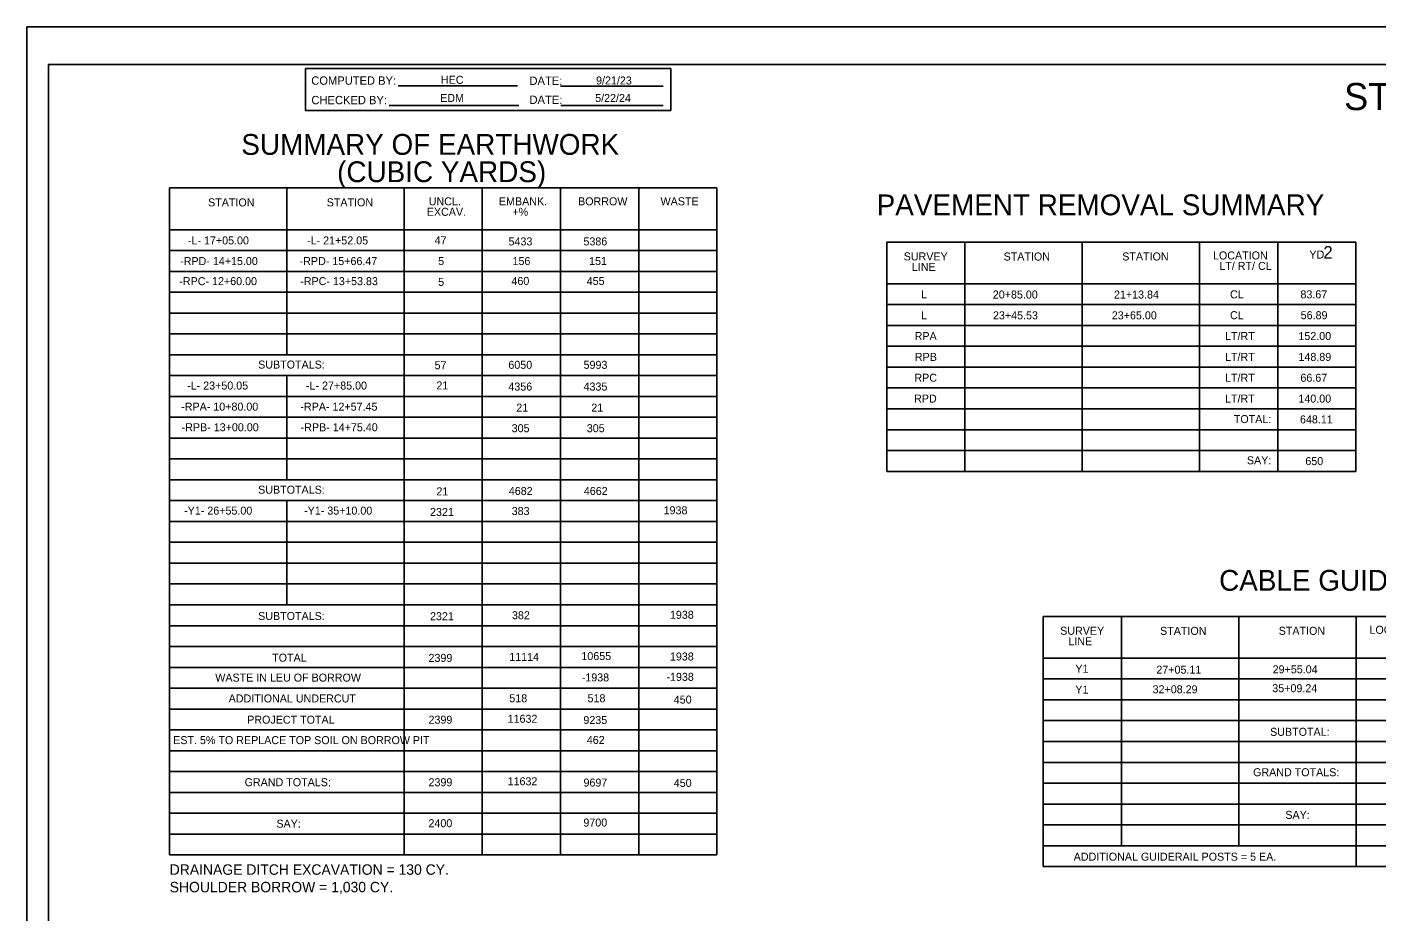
# Model space of a CAD drawing. Extents: x 2820318 to 2824860, y 680532 to 681838.
# Drawn here: x 2822504 to 2823312, y 681101 to 681632 of the extents above; entities that cross this region are included whole.
import ezdxf

# ---------------------------------------------------------------- set-up
doc = ezdxf.new("R2010")
doc.units = 0
for name, color, linetype in [('Default', 7, 'Continuous'), ('Sheet Cutting Line CELL', 7, 'Continuous'), ('Sheet Plot Border Inside CELL', 7, 'Continuous'), ('Sheet Plot Border Outside CELL', 7, 'Continuous'), ('Sheet Summary Combination CELL', 7, 'Continuous'), ('Sheet Summary Combination Grid CELL', 7, 'Continuous'), ('Sheet Summary Earthwork CELL', 7, 'Continuous')]:
    doc.layers.add(name, color=color, linetype=linetype)

msp = doc.modelspace()

# ---------------------------------------------------------------- linework, layer by layer
at = {"layer": 'Default'}
msp.add_lwpolyline([(2822503.58, 681631.51), (2822503.58, 680531.51), (2824187.58, 680531.51), (2824187.58, 681631.51)], close=True, dxfattribs=at)
msp.add_lwpolyline([(2822503.58, 681631.51), (2822503.58, 680531.51), (2824187.58, 680531.51), (2824187.58, 681631.51)], close=True, dxfattribs=at)
at = {"layer": 'Sheet Cutting Line CELL'}
for p, q in [((2824187.58, 681631.51), (2822503.58, 681631.51)), ((2822503.58, 681631.51), (2822503.58, 680531.51))]:
    msp.add_line(p, q, dxfattribs=at)
at = {"layer": 'Sheet Plot Border Inside CELL'}
msp.add_lwpolyline([(2824183.08, 681609.06), (2822516.58, 681609.06), (2822516.58, 680553.96), (2824183.08, 680553.96)], close=True, dxfattribs=at)
at = {"layer": 'Sheet Plot Border Outside CELL'}
msp.add_lwpolyline([(2824187.58, 681631.51), (2822503.58, 681631.51), (2822503.58, 680531.51), (2824187.58, 680531.51)], close=True, dxfattribs=at)
at = {"layer": 'Sheet Summary Combination CELL'}
for p, q in [((2822726.23, 681596.11), (2822797.78, 681596.11)), ((2822823.58, 681595.96), (2822884.98, 681595.96)), ((2822720.78, 681584.41), (2822798.48, 681584.41)), ((2822823.73, 681584.46), (2822885.13, 681584.46)), ((2822683.37, 681534.89), (2822683.37, 681534.89)), ((2822689.62, 681534.79), (2822689.62, 681534.79)), ((2822698.67, 681534.99), (2822698.67, 681534.99)), ((2822704.27, 681534.89), (2822704.27, 681534.89)), ((2823160.38, 681502.44), (2823160.38, 681502.44)), ((2823175.68, 681502.54), (2823175.68, 681502.54)), ((2823181.28, 681502.44), (2823181.28, 681502.44)), ((2823166.63, 681502.34), (2823166.63, 681502.34)), ((2823254.21, 681277.92), (2823254.21, 681277.92)), ((2823260.46, 681277.82), (2823260.46, 681277.82)), ((2823269.51, 681278.02), (2823269.51, 681278.02)), ((2823275.11, 681277.92), (2823275.11, 681277.92))]:
    msp.add_line(p, q, dxfattribs=at)
msp.add_lwpolyline([(2822670.58, 681606.51), (2822889.58, 681606.51), (2822889.58, 681581.51), (2822670.58, 681581.51)], close=True, dxfattribs=at)
at = {"layer": 'Sheet Summary Combination Grid CELL'}
for p, q in [((2822589.02, 681534.94), (2822917.27, 681534.94)), ((2822589.02, 681534.94), (2822589.02, 681134.94)), ((2822659.37, 681534.94), (2822659.37, 681434.94)), ((2822729.67, 681534.94), (2822729.67, 681134.94)), ((2822776.57, 681534.94), (2822776.57, 681134.94)), ((2822823.47, 681534.94), (2822823.47, 681134.94)), ((2822870.37, 681534.94), (2822870.37, 681134.94)), ((2822917.27, 681534.94), (2822917.27, 681134.94)), ((2822589.02, 681509.94), (2822917.27, 681509.94)), ((2823019.13, 681502.49), (2823300.48, 681502.49)), ((2823019.13, 681502.49), (2823019.13, 681364.99)), ((2823066.03, 681502.49), (2823066.03, 681364.99)), ((2823136.38, 681502.49), (2823136.38, 681364.99)), ((2823206.68, 681502.49), (2823206.68, 681364.99)), ((2823253.58, 681502.49), (2823253.58, 681364.99)), ((2823300.48, 681502.49), (2823300.48, 681364.99)), ((2822589.02, 681497.44), (2822917.27, 681497.44)), ((2822589.02, 681484.94), (2822917.27, 681484.94)), ((2822589.02, 681472.44), (2822917.27, 681472.44)), ((2823019.13, 681477.49), (2823300.48, 681477.49)), ((2823019.13, 681464.99), (2823300.48, 681464.99)), ((2822589.02, 681459.94), (2822917.27, 681459.94)), ((2822589.02, 681447.44), (2822917.27, 681447.44)), ((2823019.13, 681452.49), (2823300.48, 681452.49)), ((2823019.13, 681439.99), (2823300.48, 681439.99)), ((2823019.13, 681439.99), (2823300.48, 681439.99)), ((2822589.02, 681434.94), (2822917.27, 681434.94)), ((2822589.02, 681422.44), (2822917.27, 681422.44)), ((2822659.37, 681422.44), (2822659.37, 681359.94)), ((2823019.13, 681427.49), (2823300.48, 681427.49)), ((2823019.13, 681414.99), (2823300.48, 681414.99)), ((2822589.02, 681409.94), (2822917.27, 681409.94)), ((2822589.02, 681397.44), (2822917.27, 681397.44)), ((2823019.13, 681402.49), (2823300.48, 681402.49)), ((2823019.13, 681402.49), (2823300.48, 681402.49)), ((2823019.13, 681402.49), (2823300.48, 681402.49)), ((2823019.13, 681389.99), (2823300.48, 681389.99)), ((2822589.02, 681384.94), (2822917.27, 681384.94)), ((2823019.13, 681377.49), (2823300.48, 681377.49)), ((2822589.02, 681372.44), (2822917.27, 681372.44)), ((2823019.13, 681364.99), (2823300.48, 681364.99)), ((2822589.02, 681359.94), (2822917.27, 681359.94)), ((2822589.02, 681347.44), (2822917.27, 681347.44)), ((2822659.37, 681347.44), (2822659.37, 681284.94)), ((2822589.02, 681334.94), (2822917.27, 681334.94)), ((2822589.02, 681322.44), (2822917.27, 681322.44)), ((2822589.02, 681309.94), (2822917.27, 681309.94)), ((2822589.02, 681297.44), (2822917.27, 681297.44)), ((2822589.02, 681284.94), (2822917.27, 681284.94)), ((2823112.96, 681277.97), (2823597.97, 681277.97)), ((2823112.96, 681277.97), (2823112.96, 681127.97)), ((2823159.86, 681277.97), (2823159.86, 681140.47)), ((2823230.21, 681277.97), (2823230.21, 681140.47)), ((2823300.51, 681277.97), (2823300.51, 681127.97)), ((2822589.02, 681272.44), (2822917.27, 681272.44)), ((2822589.02, 681272.44), (2822917.27, 681272.44)), ((2822589.02, 681259.94), (2822917.27, 681259.94)), ((2823112.96, 681252.97), (2823597.97, 681252.97)), ((2822589.02, 681247.44), (2822917.27, 681247.44)), ((2823112.96, 681240.47), (2823597.97, 681240.47)), ((2822589.02, 681234.94), (2822917.27, 681234.94)), ((2823112.96, 681227.97), (2823551.07, 681227.97)), ((2823112.96, 681227.97), (2823597.97, 681227.97)), ((2822589.02, 681222.44), (2822917.27, 681222.44)), ((2822589.02, 681222.44), (2822917.27, 681222.44)), ((2823112.96, 681215.47), (2823597.97, 681215.47)), ((2822589.02, 681209.94), (2822917.27, 681209.94)), ((2822589.02, 681209.94), (2822917.27, 681209.94)), ((2822589.02, 681197.44), (2822917.27, 681197.44)), ((2823112.96, 681202.97), (2823597.97, 681202.97)), ((2823112.96, 681190.47), (2823597.97, 681190.47)), ((2822589.02, 681184.94), (2822917.27, 681184.94)), ((2822589.02, 681184.94), (2822917.27, 681184.94)), ((2822589.02, 681172.44), (2822917.27, 681172.44)), ((2822589.02, 681172.44), (2822917.27, 681172.44)), ((2823112.96, 681177.97), (2823597.97, 681177.97)), ((2823112.96, 681165.47), (2823597.97, 681165.47)), ((2822589.02, 681159.94), (2822917.27, 681159.94)), ((2822589.02, 681159.94), (2822917.27, 681159.94)), ((2822589.02, 681147.44), (2822917.27, 681147.44)), ((2822589.02, 681147.44), (2822917.27, 681147.44)), ((2823112.96, 681152.97), (2823597.97, 681152.97)), ((2823112.96, 681140.47), (2823551.07, 681140.47)), ((2823112.96, 681140.47), (2823597.97, 681140.47)), ((2822589.02, 681134.94), (2822917.27, 681134.94)), ((2822589.02, 681134.94), (2822917.27, 681134.94)), ((2823112.96, 681127.97), (2823597.97, 681127.97))]:
    msp.add_line(p, q, dxfattribs=at)

# ---------------------------------------------------------------- texts
at = {"layer": 'Sheet Summary Combination CELL'}
for s, height, p in [('COMPUTED BY:', 4.9998, (2822674.03, 681596.86)), ('HEC', 4.8, (2822751.79, 681597.41)), ('DATE:', 5, (2822804.88, 681596.76)), ('9/21/23', 4.8, (2822844.82, 681597.04)), ('5/22/24', 4.8, (2822844.27, 681586.5)), ('STATE OF NORTH CAROLINA', 16.2501, (2823293.33, 681581.66)), ('CHECKED BY:', 4.9998, (2822674.13, 681585.16)), ('EDM', 4.8, (2822751.33, 681586.53)), ('DATE:', 5, (2822804.88, 681585.36)), ('STATION', 4.8, (2822612.17, 681523.9)), ('STATION', 4.8, (2822683.31, 681523.92)), ('UNCL.', 4.8, (2822744.47, 681524.54)), ('EMBANK.', 4.8, (2822786.57, 681524.54)), ('BORROW', 4.8, (2822834.03, 681524.54)), ('WASTE', 4.8, (2822883.48, 681524.54)), ('EXCAV.', 4.8, (2822743.32, 681518.24)), ('+%', 4.8, (2822794.64, 681518.24)), ('-L- 17+05.00', 4.8, (2822600.09, 681501.1)), ('-L- 21+52.05', 4.8, (2822671.55, 681501.1)), ('47', 4.8, (2822748.01, 681501.19)), ('5433', 4.8, (2822792.33, 681500.5)), ('5386', 4.8, (2822837.24, 681500.5)), ('SURVEY', 4.8, (2823029.28, 681491.51)), ('STATION', 4.8, (2823089.18, 681491.45)), ('STATION', 4.8, (2823160.32, 681491.47)), ('LOCATION', 4.8, (2823214.74, 681492.09)), ('-RPD- 14+15.00', 4.8, (2822595.44, 681488.71)), ('-RPD- 15+66.47', 4.8, (2822667.07, 681488.71)), ('5', 4.8, (2822750.11, 681488.71)), ('156', 4.8, (2822794.72, 681488.71)), ('151', 4.8, (2822840.64, 681488.76)), ('LINE', 4.8, (2823034.18, 681485.21)), ('LT/ RT/ CL', 4.8, (2823218.52, 681485.79)), ('-RPC- 12+60.00', 4.8, (2822594.93, 681476.67)), ('-RPC- 13+53.83', 4.8, (2822667.42, 681476.67)), ('5', 4.8, (2822750.11, 681476.21)), ('460', 4.8, (2822794.07, 681476.76)), ('455', 4.8, (2822839.22, 681476.76)), ('L', 4.8, (2823039.67, 681468.74)), ('20+85.00', 4.8, (2823082.71, 681468.65)), ('21+13.84', 4.8, (2823155.36, 681468.65)), ('CL', 4.8, (2823224.97, 681468.74)), ('83.67', 4.8, (2823267.17, 681468.74)), ('L', 4.8, (2823039.67, 681456.24)), ('23+45.53', 4.8, (2823082.82, 681456.15)), ('23+65.00', 4.8, (2823154.08, 681456.15)), ('CL', 4.8, (2823224.97, 681456.24)), ('56.89', 4.8, (2823267.32, 681456.24)), ('RPA', 4.8, (2823035.86, 681443.74)), ('LT/RT', 4.8, (2823221.96, 681443.74)), ('152.00', 4.8, (2823265.95, 681443.74)), ('SUBTOTALS:', 4.8, (2822642.19, 681426.63)), ('57', 4.8, (2822748.01, 681426.24)), ('6050', 4.8, (2822792.23, 681426.5)), ('5993', 4.8, (2822837.33, 681426.5)), ('RPB', 4.8, (2823035.99, 681431.24)), ('LT/RT', 4.8, (2823221.96, 681431.24)), ('148.89', 4.8, (2823265.99, 681431.24)), ('RPC', 4.8, (2823035.7, 681418.74)), ('LT/RT', 4.8, (2823221.96, 681418.74)), ('66.67', 4.8, (2823267.17, 681418.74)), ('-L- 23+50.05', 4.8, (2822599.61, 681414.05)), ('-L- 27+85.00', 4.8, (2822670.88, 681414.05)), ('21', 4.8, (2822749.06, 681414.14)), ('4356', 4.8, (2822792.24, 681413.45)), ('4335', 4.8, (2822837.32, 681413.45)), ('-RPA- 10+80.00', 4.8, (2822596.05, 681401.4)), ('-RPA- 12+57.45', 4.8, (2822667.52, 681401.4)), ('21', 4.8, (2822796.97, 681400.8)), ('21', 4.8, (2822841.97, 681400.8)), ('RPD', 4.8, (2823035.52, 681406.24)), ('LT/RT', 4.8, (2823221.96, 681406.24)), ('140.00', 4.8, (2823265.95, 681406.24)), ('TOTAL:', 4.8, (2823227.23, 681393.94)), ('648.11', 4.8, (2823266.9, 681393.74)), ('-RPB- 13+00.00', 4.8, (2822596.32, 681389.05)), ('-RPB- 14+75.40', 4.8, (2822667.69, 681389.05)), ('305', 4.8, (2822794.22, 681388.46)), ('305', 4.8, (2822839.27, 681388.46)), ('SAY:', 4.8, (2823235.08, 681369.23)), ('650', 4.8, (2823270.13, 681368.74)), ('SUBTOTALS:', 4.8, (2822642.19, 681351.59)), ('21', 4.8, (2822749.06, 681350.58)), ('4682', 4.8, (2822792.49, 681350.84)), ('4662', 4.8, (2822837.48, 681350.84)), ('-Y1- 26+55.00', 4.8, (2822597.81, 681339.05)), ('-Y1- 35+10.00', 4.8, (2822669.75, 681339.05)), ('2321', 4.8, (2822745.27, 681338.23)), ('383', 4.8, (2822794.23, 681338.79)), ('1938', 4.8, (2822885.32, 681339.24)), ('SUBTOTALS:', 4.8, (2822642.19, 681275.84)), ('2321', 4.8, (2822745.27, 681275.73)), ('382', 4.8, (2822794.39, 681276.29)), ('1938', 4.8, (2822889.1, 681276.55)), ('SURVEY', 4.8, (2823123.11, 681266.98)), ('STATION', 4.8, (2823183.01, 681266.93)), ('STATION', 4.8, (2823254.15, 681266.95)), ('LOCATION', 4.8, (2823308.57, 681267.57)), ('LINE', 4.8, (2823128.02, 681260.68)), ('TOTAL', 4.8, (2822650.6, 681250.84)), ('2399', 4.8, (2822744.36, 681250.73)), ('11114', 4.8, (2822792.76, 681251.29)), ('10655', 4.8, (2822836, 681251.81)), ('1938', 4.8, (2822889.1, 681251.55)), ('WASTE IN LEU OF BORROW', 4.8, (2822616.47, 681238.89)), ('-1938', 4.8, (2822836.23, 681239.01)), ('-1938', 4.8, (2822887.02, 681239.36)), ('Y1', 4.8, (2823132.21, 681244.22)), ('27+05.11', 4.8, (2823180.8, 681243.64)), ('29+55.04', 4.8, (2823250.52, 681243.86)), ('Y1', 4.8, (2823132.21, 681231.72)), ('32+08.29', 4.8, (2823178.53, 681231.88)), ('35+09.24', 4.8, (2823250.3, 681232.54)), ('ADDITIONAL UNDERCUT', 4.8, (2822624.5, 681226.39)), ('518', 4.8, (2822792.8, 681226.51)), ('518', 4.8, (2822839.7, 681226.51)), ('450', 4.8, (2822891.41, 681225.73)), ('PROJECT TOTAL', 4.8, (2822635.63, 681213.66)), ('2399', 4.8, (2822744.36, 681213.64)), ('11632', 4.8, (2822791.77, 681214.2)), ('9235', 4.8, (2822837.21, 681213.45)), ('SUBTOTAL:', 4.8, (2823248.98, 681206.37)), ('EST. 5% TO REPLACE TOP SOIL ON BORROW PIT', 4.8, (2822591.26, 681201.39)), ('462', 4.8, (2822839.27, 681201.51)), ('GRAND TOTALS:', 4.8, (2823238.78, 681182.14)), ('GRAND TOTALS:', 4.8, (2822634.08, 681176.16)), ('2399', 4.8, (2822744.36, 681176.14)), ('11632', 4.8, (2822791.77, 681176.7)), ('9697', 4.8, (2822837.28, 681175.95)), ('450', 4.8, (2822891.41, 681175.73)), ('SAY:', 4.8, (2822653.15, 681151.29)), ('2400', 4.8, (2822744.32, 681151.56)), ('9700', 4.8, (2822837.22, 681151.96)), ('SAY:', 4.8, (2823258.12, 681156.56)), ('ADDITIONAL GUIDERAIL POSTS = 5 EA.', 4.8, (2823131.21, 681131.49))]:
    msp.add_text(s, height=height, dxfattribs=at).set_placement(p)
for s, p in [('SUMMARY OF EARTHWORK', (2822632.09, 681554.81)), ('(CUBIC YARDS)', (2822689.54, 681538.43)), ('PAVEMENT REMOVAL SUMMARY', (2823013.06, 681518.55)), ('CABLE GUIDERAIL SUMMARY', (2823218.41, 681293.37))]:
    msp.add_text(s, height=12.5001, rotation=0.01193, dxfattribs=at).set_placement(p)
at = {"layer": 'Sheet Summary Combination Grid CELL'}
for s, height, p in [('YD', 4.8, (2823272.54, 681492.62)), ('2', 7.5, (2823280.91, 681492.62))]:
    msp.add_text(s, height=height, dxfattribs=at).set_placement(p)
at = {"layer": 'Sheet Summary Earthwork CELL'}
for s, p in [('DRAINAGE DITCH EXCAVATION = 130 CY.', (2822589.14, 681123.04)), ('SHOULDER BORROW = 1,030 CY.', (2822589.14, 681112.54))]:
    msp.add_text(s, height=6.25, dxfattribs=at).set_placement(p)

doc.saveas('drawing.dxf')
